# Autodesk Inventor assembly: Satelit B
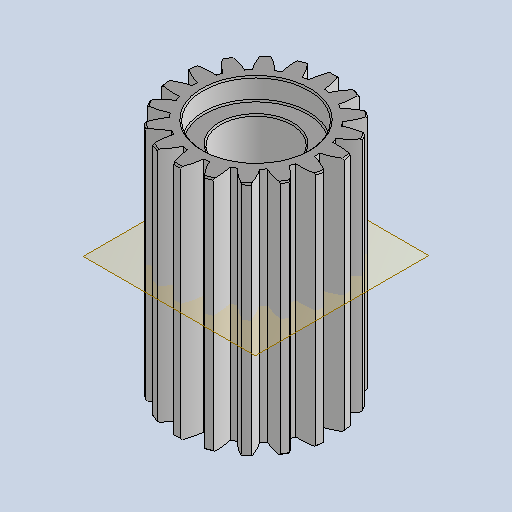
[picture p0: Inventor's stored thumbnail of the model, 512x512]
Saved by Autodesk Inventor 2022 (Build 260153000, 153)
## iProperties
Created: 2025-05
Part Number: Satelit B
Document SubType Name: Assembly
Designer: jbart
Mass: 1135.55 g
Surface Area: 1687.53 cm^2
Volume: 1135.55 cm^3
Density: 1 g/cm^3
Author: jbart
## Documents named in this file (2)
- C:\Users\jbart\OneDrive\Dokumenty\Inventor\Převodovka navijáku\Satelit B.iam
- C:\Users\jbart\OneDrive\Dokumenty\Inventor\Převodovka navijáku\Satelit B\Design Accelerator\Čelní ozubená kola1.iam
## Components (1 placed, 1 different names)
1. Čelní ozubená kola:1 [sub-assembly]
